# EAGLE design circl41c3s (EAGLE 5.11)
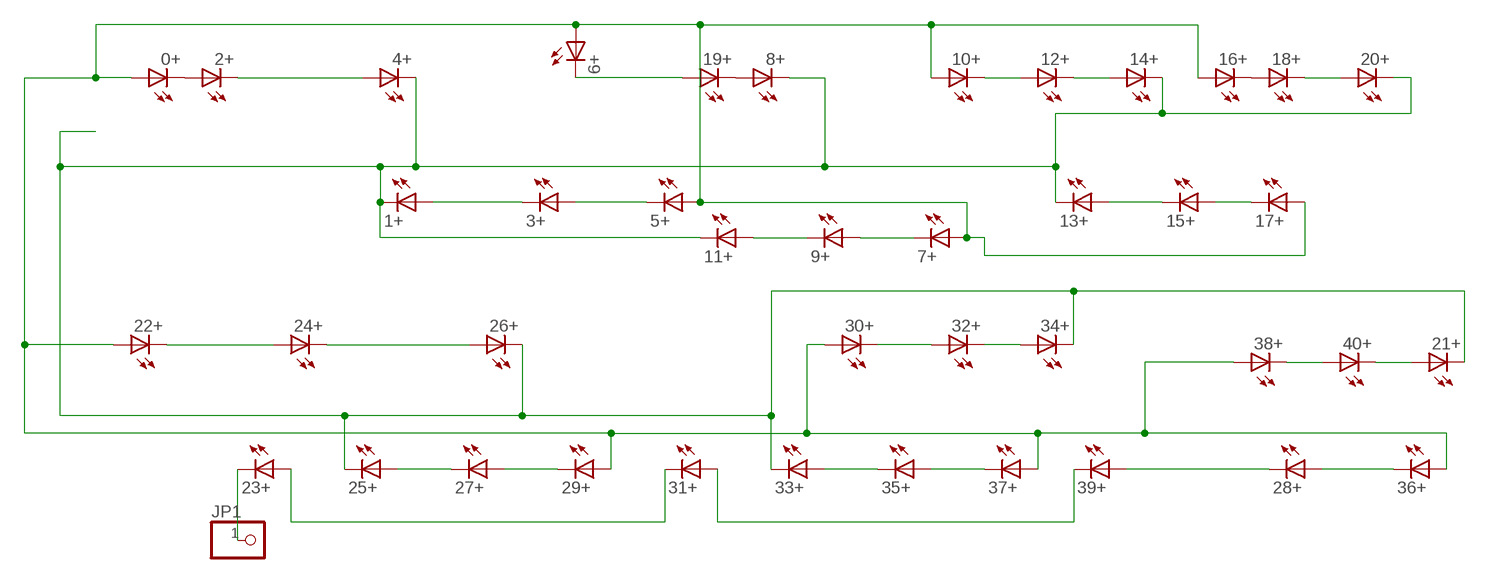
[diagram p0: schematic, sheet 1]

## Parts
0+  LED5MM  [LED5MM]
1+  LED5MM  [LED5MM]
2+  LED5MM  [LED5MM]
3+  LED5MM  [LED5MM]
4+  LED5MM  [LED5MM]
5+  LED5MM  [LED5MM]
6+  LED5MM  [LED5MM]
7+  LED5MM  [LED5MM]
8+  LED5MM  [LED5MM]
9+  LED5MM  [LED5MM]
10+  LED5MM  [LED5MM]
11+  LED5MM  [LED5MM]
12+  LED5MM  [LED5MM]
13+  LED5MM  [LED5MM]
14+  LED5MM  [LED5MM]
15+  LED5MM  [LED5MM]
16+  LED5MM  [LED5MM]
17+  LED5MM  [LED5MM]
18+  LED5MM  [LED5MM]
19+  LED5MM  [LED5MM]
20+  LED5MM  [LED5MM]
21+  LED5MM  [LED5MM]
22+  LED5MM  [LED5MM]
23+  LED5MM  [LED5MM]
24+  LED5MM  [LED5MM]
25+  LED5MM  [LED5MM]
26+  LED5MM  [LED5MM]
27+  LED5MM  [LED5MM]
28+  LED5MM  [LED5MM]
29+  LED5MM  [LED5MM]
30+  LED5MM  [LED5MM]
31+  LED5MM  [LED5MM]
32+  LED5MM  [LED5MM]
33+  LED5MM  [LED5MM]
34+  LED5MM  [LED5MM]
35+  LED5MM  [LED5MM]
36+  LED5MM  [LED5MM]
37+  LED5MM  [LED5MM]
38+  LED5MM  [LED5MM]
39+  LED5MM  [LED5MM]
40+  LED5MM  [LED5MM]
JP1  PINHD-1X1M  [1X01M]

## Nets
MINUS: 1+.K(C) 4+.K(C) 8+.K(C) 11+.K(C) 13+.K(C) 14+.K(C) 20+.K(C) 21+.K(C) 25+.K(C) 26+.K(C) 33+.K(C) 34+.K(C)
N$1: 31+.A 39+.K(C)
N$2: 28+.K(C) 39+.A
N$3: 28+.A 36+.K(C)
N$4: 23+.K(C) JP1.1
N$6: 35+.A 37+.K(C)
N$7: 33+.A 35+.K(C)
N$8: 27+.A 29+.K(C)
N$9: 25+.A 27+.K(C)
N$12: 23+.A 31+.K(C)
N$13: 38+.K(C) 40+.A
N$14: 32+.K(C) 34+.A
N$15: 30+.K(C) 32+.A
N$16: 3+.A 5+.K(C)
N$17: 1+.A 3+.K(C)
N$18: 21+.A 40+.K(C)
N$20: 22+.K(C) 24+.A
N$21: 24+.K(C) 26+.A
N$22: 7+.K(C) 9+.A
N$23: 9+.K(C) 11+.A
N$24: 13+.A 15+.K(C)
N$25: 15+.A 17+.K(C)
N$28: 18+.K(C) 20+.A
N$29: 16+.K(C) 18+.A
N$30: 10+.K(C) 12+.A
N$31: 12+.K(C) 14+.A
N$33: 6+.K(C) 19+.A
N$34: 8+.A 19+.K(C)
N$35: 2+.K(C) 4+.A
N$36: 0+.K(C) 2+.A
PLUS: 0+.A 5+.A 6+.A 7+.A 10+.A 16+.A 17+.A 22+.A 29+.A 30+.A 36+.A 37+.A 38+.A

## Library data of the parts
0+ 1+ 2+ 3+ 4+ 5+ 6+ 7+ 8+ 9+ 10+ 11+ 12+ 13+ 14+ 15+ 16+ 17+ 18+ 19+ 20+ 21+ 22+ 23+ 24+ 25+ 26+ 27+ 28+ 29+ 30+ 31+ 32+ 33+ 34+ 35+ 36+ 37+ 38+ 39+ 40+ = led(2):LED: LED
JP1 = pinhead(2):PINHD-1X1: PIN HEADER

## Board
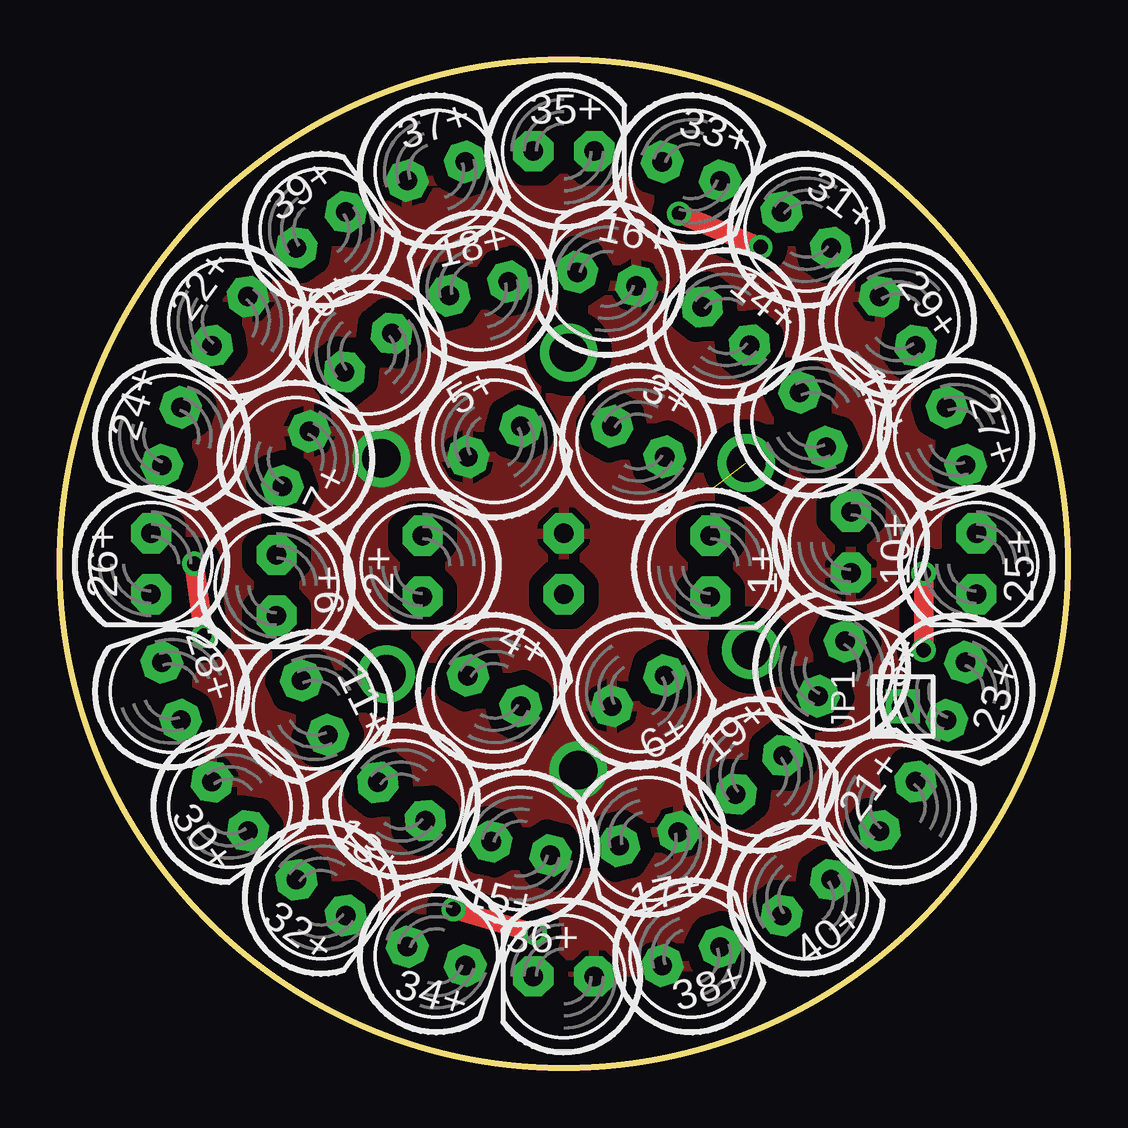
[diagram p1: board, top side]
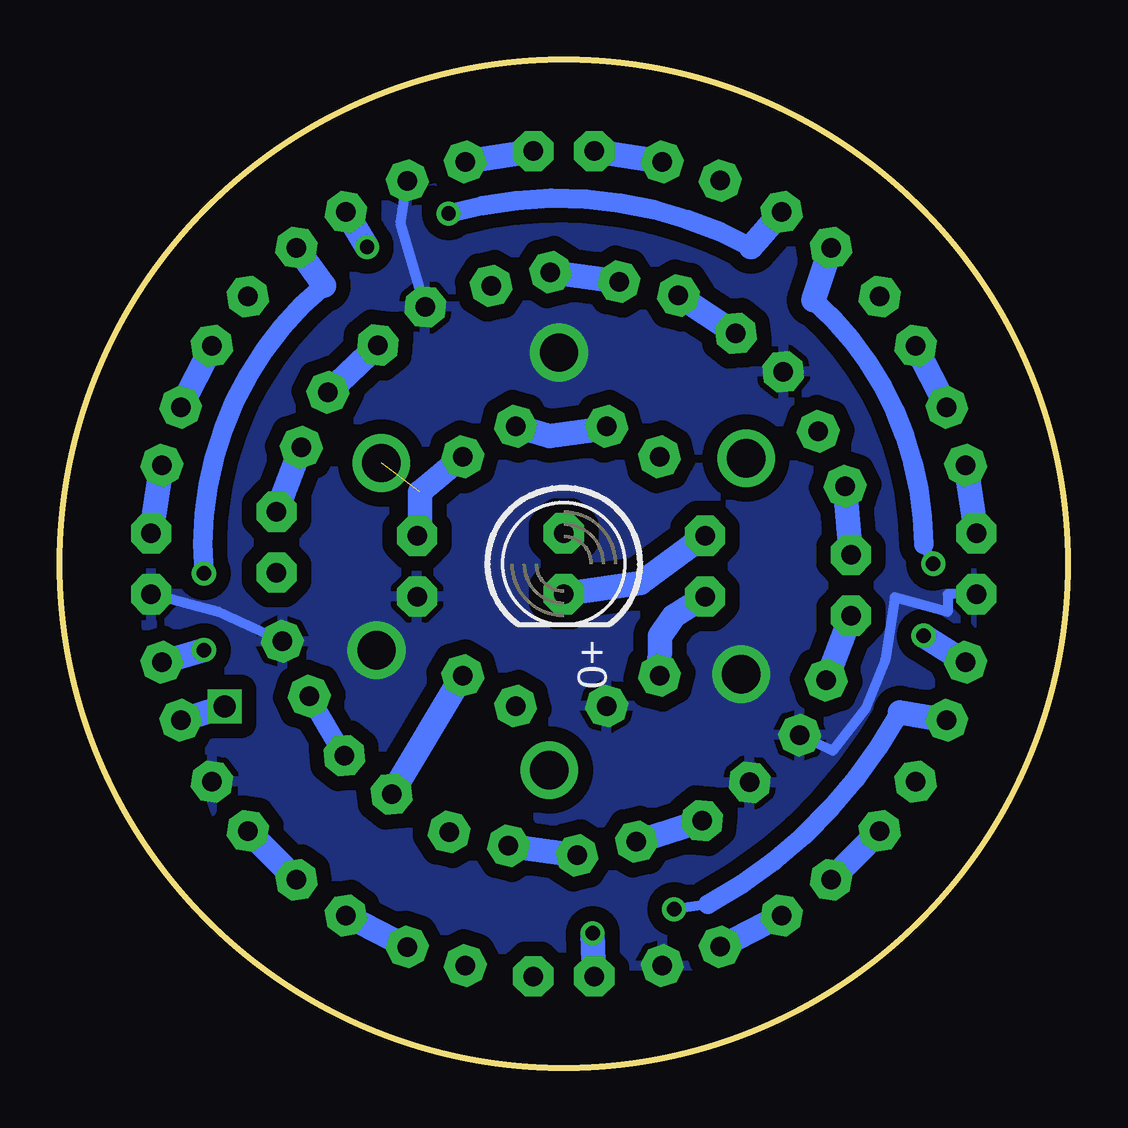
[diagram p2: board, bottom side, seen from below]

Size 42 x 42 mm. Coordinates in mm from the lower left corner, seen from the top.
Outline: circle at 21,21 radius 21
Copper layers (1*16): Top 0.035mm / dielectric 1.5mm / Bottom 0.035mm
Design rules "default": minimum track width 10mil, minimum drill 24mil, track to track 8mil, track to pad 8mil, pad to pad 8mil, via to via 8mil, smd to smd 8mil, copper to edge 40mil, drill to drill 8mil, minimum pad ring 10mil, minimum via ring 8mil, stop-mask expansion 4mil, vias tented up to drill 0mil, thermal gap 10mil

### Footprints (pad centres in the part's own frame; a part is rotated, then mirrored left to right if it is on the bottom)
LED5MM = drill 0.813 pad 1.676 octagon: A -1.27,0; K 1.27,0
1X01M = drill 0.914 square: 1 0,0

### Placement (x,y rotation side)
0+  21,21 270 bottom
1+  27.11,20.9 270 top
2+  15.11,20.9 270 top
3+  24.11,26.1 330 top
4+  18.11,15.7 330 top
5+  18.11,26.1 30 top
6+  24.11,15.7 30 top
7+  9.83,25.38 244 top
8+  32.17,16.62 64 top
9+  9.03,20.1 270 top
10+  32.97,21.9 90 top
11+  10.61,15 296 top
12+  31.39,27 116 top
13+  14.24,11.09 141 top
14+  27.76,30.91 141 top
15+  19.21,9.13 167 top
16+  22.79,32.87 167 top
17+  24.54,9.53 193 top
18+  17.46,32.47 193 top
19+  29.16,12.2 39 top
20+  12.84,29.8 219 top
21+  34.92,10.89 54 top
22+  7.08,31.11 234 top
23+  37.36,15.68 252 top
24+  4.64,26.32 252 top
25+  38.2,21 270 top
26+  3.8,21 270 top
27+  37.36,26.32 288 top
28+  4.64,15.68 108 top
29+  34.92,31.11 306 top
30+  7.08,10.89 306 top
31+  31.11,34.92 324.1 top
32+  10.89,7.08 324.1 top
33+  26.32,37.36 342 top
34+  15.68,4.64 342 top
35+  21,38.2 0 top
36+  21,3.8 180 top
37+  15.68,37.36 17.9 top
38+  26.32,4.64 17.9 top
39+  10.89,34.92 35.9 top
40+  31.11,7.08 35.9 top
JP1  35.14,15.05 0 top

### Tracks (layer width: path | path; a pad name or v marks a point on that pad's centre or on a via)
MINUS  (via drill 1.6)
  Bottom 0.406: 26+.K 5,19.73 5,19 7.2,19.6 7.6,17 8.4,15 9.8,13.2 11+.K | 25+.K 35.4,19 8+.K | 33+.K 27.8,35.2 14+.K
  other vias: 13.6,16.4 28.8,17.4 21.2,29.8
  pour Bottom (isolate 0.61): 17,39 29,36 37.4,29 38.8,19.4 35,9.2 27,4.4 16,4 7,11 4,18 4,25 10,36 14,38
N$1  (via drill 0.6)
  Top 0.813: v25.8,35.6 v29.2,34.2
  Bottom 0.813: 13.2,34.2 arc-44 v25.8,35.6
  Bottom 1.016: 39+.K 13.2,34.2 | v29.2,34.2 31+.A
N$2  (via drill 0.6)
  Top 0.813: v6,18 v5.6,21
  Bottom 0.406: v5.6,21 6,21.8
  Bottom 0.813: 6,21.8 arc-48 10.6,32
  Bottom 1.016: 10.6,32 39+.A | 28+.K v6,18
N$3  (via drill 0.6)
  Top 0.813: v16.4,6.6 v19.8,5.6
  Bottom 0.406: 15,6.8 v16.4,6.6
  Bottom 0.813: 7,14.8 arc33 15,6.8
  Bottom 1.016: 28+.A 7,14.8 | v19.8,5.6 36+.K
N$4
  Bottom 1.016: JP1.1 23+.K
N$6
  Bottom 1.016: 37+.K 35+.A
N$7
  Bottom 1.016: 33+.A 35+.K
N$8
  Bottom 1.016: 27+.A 29+.K
N$9
  Bottom 1.016: 25+.A 27+.K
N$12  (via drill 0.6)
  Top 0.813: v36,17.4 v36,20.6
  Bottom 0.813: v36,20.6 arc55 31,32.6
  Bottom 1.016: 31,32.6 31+.K | 23+.A v36,17.4
N$13
  Bottom 1.016: 38+.K 40+.A
N$14
  Bottom 1.016: 32+.K 34+.A
N$15
  Bottom 1.016: 30+.K 32+.A
N$16
  Bottom 1.016: 5+.K 19.6,26.6 21.6,26.33 3+.A
N$17  (via drill 1.6)  (1 unrouted)
  Bottom 1.016: 1+.A 27,22.17 27,24 3+.K
  other vias: 28.6,25.2
N$18
  Bottom 1.016: 40+.K 21+.A
N$20
  Bottom 1.016: 24+.A 22+.K
N$21
  Bottom 1.016: 26+.A 24+.K
N$22
  Bottom 1.016: 9+.A 7+.K
N$23
  Bottom 1.016: 11+.A 9+.K
N$24
  Bottom 1.016: 13+.A 15+.K
N$25
  Bottom 1.016: 15+.A 17+.K
N$28
  Bottom 1.016: 20+.A 18+.K
N$29
  Bottom 1.016: 18+.A 16+.K
N$30
  Bottom 1.016: 10+.K 12+.A
N$31
  Bottom 1.016: 14+.A 12+.K
N$33
  Bottom 1.016: 19+.A 6+.K
N$34
  Bottom 0.813: 19+.K 8+.A
N$35
  Bottom 1.016: 4+.A 17,18 16.4,18.83 2+.K
N$36
  Bottom 1.016: 0+.K 17.8,20.2 2+.A
PLUS  (via drill 1.6, 1.6 pad 0.25)
  other vias: 21.6,12.4 13.4,25.4
  pour Top (isolate 0.61): 17,38 28,37 36,30 38,20 35,10 26,4 15,4 7,11 4,17 4,24 7,32 12,36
